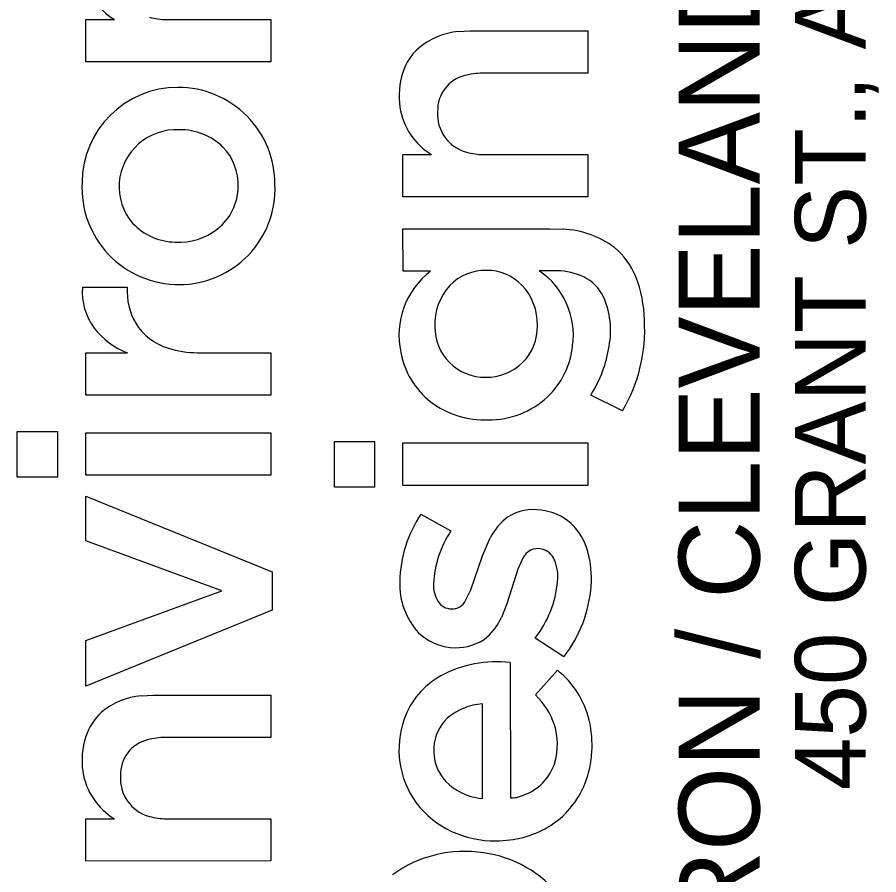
# Model space of a CAD drawing. Extents: x -0.2 to 34, y 0 to 22.
# Drawn here: x 32.377 to 32.984, y 3.278 to 3.882 of the extents above; entities that cross this region are included whole.
import ezdxf

# ---------------------------------------------------------------- set-up
doc = ezdxf.new("R2010")
doc.units = 0
doc.layers.add('RW_X_Esmt_SH', color=7, linetype='Continuous')

msp = doc.modelspace()

# ---------------------------------------------------------------- linework, layer by layer
at = {"layer": 'RW_X_Esmt_SH'}
for p, q in [((32.42542, 3.88066), (32.44552, 3.88071)), ((32.42542, 3.85086), (32.42542, 3.88066)), ((32.48222, 3.88071), (32.55569, 3.88071)), ((32.55569, 3.88071), (32.55571, 3.85096)), ((32.68784, 3.8722), (32.69634, 3.87266)), ((32.69634, 3.87266), (32.77916, 3.87266)), ((32.77916, 3.87266), (32.77917, 3.84287)), ((32.55571, 3.85096), (32.42542, 3.85086)), ((32.77917, 3.84287), (32.70485, 3.8428)), ((32.64888, 3.7855), (32.66897, 3.78555)), ((32.64888, 3.75569), (32.64888, 3.7855)), ((32.70568, 3.78555), (32.77915, 3.78555)), ((32.77915, 3.78555), (32.77917, 3.75579)), ((32.77917, 3.75579), (32.64888, 3.75569)), ((32.6489, 3.70336), (32.64889, 3.73322)), ((32.64889, 3.73322), (32.75236, 3.73322)), ((32.75236, 3.73322), (32.76191, 3.73285)), ((32.66836, 3.70336), (32.6489, 3.70336)), ((32.75763, 3.70356), (32.74487, 3.70361)), ((32.42299, 3.69193), (32.45454, 3.69193)), ((32.42542, 3.64577), (32.45473, 3.64579)), ((32.42542, 3.61593), (32.42542, 3.64577)), ((32.50413, 3.64581), (32.55571, 3.64573)), ((32.55571, 3.64573), (32.55565, 3.61593)), ((32.55565, 3.61593), (32.42542, 3.61593)), ((32.8036, 3.60491), (32.7812, 3.61598)), ((32.37705, 3.55818), (32.37705, 3.59026)), ((32.37705, 3.59026), (32.40543, 3.59026)), ((32.40543, 3.59026), (32.40543, 3.55818)), ((32.42542, 3.55942), (32.42542, 3.58928)), ((32.42542, 3.58928), (32.55571, 3.58928)), ((32.55571, 3.58928), (32.55571, 3.55942)), ((32.60051, 3.55111), (32.60051, 3.58319)), ((32.60051, 3.58319), (32.62889, 3.58319)), ((32.62889, 3.58319), (32.62889, 3.55111)), ((32.64888, 3.55234), (32.64888, 3.5822)), ((32.64888, 3.5822), (32.77917, 3.5822)), ((32.77917, 3.5822), (32.77917, 3.55234)), ((32.40543, 3.55818), (32.37705, 3.55818)), ((32.55571, 3.55942), (32.42542, 3.55942)), ((32.77917, 3.55234), (32.64888, 3.55234)), ((32.62889, 3.55111), (32.60051, 3.55111)), ((32.42542, 3.51327), (32.42542, 3.5446)), ((32.42542, 3.5446), (32.5567, 3.4913)), ((32.66151, 3.53207), (32.68268, 3.52025)), ((32.70483, 3.50258), (32.71036, 3.51526)), ((32.52117, 3.47798), (32.42542, 3.51327)), ((32.69675, 3.47868), (32.70483, 3.50258)), ((32.73342, 3.50101), (32.72985, 3.4933)), ((32.5567, 3.4913), (32.5567, 3.46441)), ((32.72985, 3.4933), (32.72213, 3.46882)), ((32.42542, 3.44294), (32.52117, 3.47798)), ((32.69299, 3.47117), (32.69675, 3.47868)), ((32.72213, 3.46882), (32.71822, 3.45921)), ((32.5567, 3.46441), (32.42542, 3.41086)), ((32.42542, 3.41086), (32.42542, 3.44294)), ((32.76214, 3.43141), (32.74198, 3.44469)), ((32.72453, 3.42747), (32.72463, 3.33195)), ((32.74228, 3.40465), (32.75768, 3.422)), ((32.46439, 3.40397), (32.47289, 3.40443)), ((32.47289, 3.40443), (32.55571, 3.40443)), ((32.55571, 3.40443), (32.55571, 3.37465)), ((32.70489, 3.33182), (32.70489, 3.39834)), ((32.55571, 3.37465), (32.4814, 3.37457)), ((32.70361, 3.33165), (32.70489, 3.33182)), ((32.42542, 3.31728), (32.44552, 3.31733)), ((32.42542, 3.28747), (32.42542, 3.31728)), ((32.48222, 3.31733), (32.55569, 3.31733)), ((32.55569, 3.31733), (32.55571, 3.28756)), ((32.55571, 3.28756), (32.42542, 3.28747))]:
    msp.add_line(p, q, dxfattribs=at)
for points in [[(32.42542, 3.85086), (32.42542, 3.88066), (32.44552, 3.88071)], [(32.48222, 3.88071), (32.55569, 3.88071), (32.55571, 3.85096), (32.42542, 3.85086)], [(32.68784, 3.8722), (32.69634, 3.87266), (32.77916, 3.87266), (32.77917, 3.84287), (32.70485, 3.8428)], [(32.64888, 3.75569), (32.64888, 3.7855), (32.66897, 3.78555)], [(32.70568, 3.78555), (32.77915, 3.78555), (32.77917, 3.75579), (32.64888, 3.75569)], [(32.66836, 3.70336), (32.6489, 3.70336), (32.64889, 3.73322), (32.75236, 3.73322), (32.76191, 3.73285)], [(32.75763, 3.70356), (32.74487, 3.70361)], [(32.42299, 3.69193), (32.45454, 3.69193)], [(32.50413, 3.64581), (32.55571, 3.64573), (32.55565, 3.61593), (32.42542, 3.61593)], [(32.42542, 3.61593), (32.42542, 3.64577), (32.45473, 3.64579)], [(32.8036, 3.60491), (32.7812, 3.61598)], [(32.66151, 3.53207), (32.68268, 3.52025)], [(32.69299, 3.47117), (32.69675, 3.47868), (32.70483, 3.50258), (32.71036, 3.51526)], [(32.73342, 3.50101), (32.72985, 3.4933), (32.72213, 3.46882), (32.71822, 3.45921)], [(32.76214, 3.43141), (32.74198, 3.44469)], [(32.72453, 3.42747), (32.72463, 3.33195)], [(32.74228, 3.40465), (32.75768, 3.422)], [(32.46439, 3.40397), (32.47289, 3.40443), (32.55571, 3.40443), (32.55571, 3.37465), (32.4814, 3.37457)], [(32.70361, 3.33165), (32.70489, 3.33182), (32.70489, 3.39834)], [(32.42542, 3.28747), (32.42542, 3.31728), (32.44552, 3.31733)], [(32.48222, 3.31733), (32.55569, 3.31733), (32.55571, 3.28756), (32.42542, 3.28747)]]:
    msp.add_lwpolyline(points, dxfattribs=at)
for points in [[(32.37705, 3.55818), (32.37705, 3.59026), (32.40543, 3.59026), (32.40543, 3.55818)], [(32.42542, 3.55942), (32.42542, 3.58928), (32.55571, 3.58928), (32.55571, 3.55942)], [(32.60051, 3.55111), (32.60051, 3.58319), (32.62889, 3.58319), (32.62889, 3.55111)], [(32.64888, 3.55234), (32.64888, 3.5822), (32.77917, 3.5822), (32.77917, 3.55234)], [(32.42542, 3.41086), (32.42542, 3.44294), (32.52117, 3.47798), (32.42542, 3.51327), (32.42542, 3.5446), (32.5567, 3.4913), (32.5567, 3.46441)]]:
    msp.add_lwpolyline(points, close=True, dxfattribs=at)
for centre, radius, start, end in [((32.47027, 3.92141), 0.04763, 188.96462, 238.69865), ((32.47027, 3.92141), 0.04763, 188.96462, 238.69865), ((32.48183, 3.92286), 0.04215, 254.08913, 270.52838), ((32.48183, 3.92286), 0.04215, 254.08913, 270.52838), ((32.69216, 3.82251), 0.04988, 94.97056, 130.22484), ((32.69216, 3.82251), 0.04988, 94.97056, 130.22484), ((32.68694, 3.83085), 0.04016, 132.22383, 161.68229), ((32.68694, 3.83085), 0.04016, 132.22383, 161.68229), ((32.70217, 3.82642), 0.05602, 162.27398, 187.79173), ((32.70217, 3.82642), 0.05602, 162.27398, 187.79173), ((32.69828, 3.81689), 0.02498, 103.68683, 182.21395), ((32.69828, 3.81689), 0.02498, 103.68683, 182.21395), ((32.70453, 3.79679), 0.04601, 89.60515, 105.33026), ((32.70453, 3.79679), 0.04601, 89.60515, 105.33026), ((32.49014, 3.76543), 0.0674, 89.84756, 179.64047), ((32.49014, 3.76543), 0.0674, 89.84756, 179.64047), ((32.49057, 3.76474), 0.0681, 359.54009, 90.21138), ((32.49057, 3.76474), 0.0681, 359.54009, 90.21138), ((32.69372, 3.82624), 0.04763, 188.96462, 238.69865), ((32.69372, 3.82624), 0.04763, 188.96462, 238.69865), ((32.7008, 3.81381), 0.02757, 175.58441, 255.13816), ((32.7008, 3.81381), 0.02757, 175.58441, 255.13816), ((32.48923, 3.76263), 0.0404, 87.04809, 175.57259), ((32.48923, 3.76263), 0.0404, 87.04809, 175.57259), ((32.49204, 3.75999), 0.04299, 45.84264, 90.98008), ((32.49204, 3.75999), 0.04299, 45.84264, 90.98008), ((32.49458, 3.76421), 0.03821, 357.88569, 44.15902), ((32.49458, 3.76421), 0.03821, 357.88569, 44.15902), ((32.70529, 3.82769), 0.04215, 254.08913, 270.52838), ((32.70529, 3.82769), 0.04215, 254.08913, 270.52838), ((32.49083, 3.76209), 0.06819, 176.8344, 270.40384), ((32.49083, 3.76209), 0.06819, 176.8344, 270.40384), ((32.48729, 3.7625), 0.03848, 175.15378, 221.14706), ((32.48729, 3.7625), 0.03848, 175.15378, 221.14706), ((32.49123, 3.76139), 0.06749, 270.06243, 2.37759), ((32.49123, 3.76139), 0.06749, 270.06243, 2.37759), ((32.49446, 3.76318), 0.0383, 308.28936, 359.43468), ((32.49446, 3.76318), 0.0383, 308.28936, 359.43468), ((32.48919, 3.76607), 0.04228, 223.09994, 268.80895), ((32.48919, 3.76607), 0.04228, 223.09994, 268.80895), ((32.49096, 3.7679), 0.04418, 266.56515, 308.06078), ((32.49096, 3.7679), 0.04418, 266.56515, 308.06078), ((32.75907, 3.66789), 0.06503, 53.40344, 87.49062), ((32.75907, 3.66789), 0.06503, 53.40344, 87.49062), ((32.76517, 3.68039), 0.05141, 21.60748, 50.5577), ((32.76517, 3.68039), 0.05141, 21.60748, 50.5577), ((32.70292, 3.65813), 0.05692, 127.37482, 192.22468), ((32.70292, 3.65813), 0.05692, 127.37482, 192.22468), ((32.70693, 3.66927), 0.0346, 88.47302, 136.42562), ((32.70693, 3.66927), 0.0346, 88.47302, 136.42562), ((32.70814, 3.66963), 0.03424, 44.27195, 90.47623), ((32.70814, 3.66963), 0.03424, 44.27195, 90.47623), ((32.71421, 3.65829), 0.05472, 352.1125, 55.92295), ((32.71421, 3.65829), 0.05472, 352.1125, 55.92295), ((32.75666, 3.65725), 0.04633, 65.01687, 88.8011), ((32.75666, 3.65725), 0.04633, 65.01687, 88.8011), ((32.7626, 3.67155), 0.03085, 26.26808, 63.80301), ((32.7626, 3.67155), 0.03085, 26.26808, 63.80301), ((32.73069, 3.66714), 0.08835, 1.15143, 21.3627), ((32.73069, 3.66714), 0.08835, 1.15143, 21.3627), ((32.46616, 3.68882), 0.04329, 175.87313, 216.34747), ((32.46616, 3.68882), 0.04329, 175.87313, 216.34747), ((32.50087, 3.68948), 0.04639, 176.9688, 209.60636), ((32.50087, 3.68948), 0.04639, 176.9688, 209.60636), ((32.71141, 3.66602), 0.0401, 137.46739, 182.33237), ((32.71141, 3.66602), 0.0401, 137.46739, 182.33237), ((32.70368, 3.666), 0.03996, 358.57141, 43.53765), ((32.70368, 3.666), 0.03996, 358.57141, 43.53765), ((32.73565, 3.66154), 0.05953, 349.30734, 23.43071), ((32.73565, 3.66154), 0.05953, 349.30734, 23.43071), ((32.70538, 3.66244), 0.11383, 329.6388, 3.25998), ((32.70538, 3.66244), 0.11383, 329.6388, 3.25998), ((32.47466, 3.69716), 0.05511, 218.09809, 248.7907), ((32.47466, 3.69716), 0.05511, 218.09809, 248.7907), ((32.49514, 3.68814), 0.04079, 211.94466, 253.2028), ((32.49514, 3.68814), 0.04079, 211.94466, 253.2028), ((32.70645, 3.6637), 0.03511, 178.88208, 271.08374), ((32.70645, 3.6637), 0.03511, 178.88208, 271.08374), ((32.70818, 3.66404), 0.03546, 268.27882, 1.55016), ((32.70818, 3.66404), 0.03546, 268.27882, 1.55016), ((32.50465, 3.7165), 0.07069, 252.46555, 269.57296), ((32.50465, 3.7165), 0.07069, 252.46555, 269.57296), ((32.70988, 3.65708), 0.05887, 313.74196, 353.8554), ((32.70988, 3.65708), 0.05887, 313.74196, 353.8554), ((32.70738, 3.66334), 0.08771, 327.31495, 351.57478), ((32.70738, 3.66334), 0.08771, 327.31495, 351.57478), ((32.70463, 3.65696), 0.05837, 190.75182, 231.28919), ((32.70463, 3.65696), 0.05837, 190.75182, 231.28919), ((32.70954, 3.65901), 0.06051, 269.6361, 312.70877), ((32.70954, 3.65901), 0.06051, 269.6361, 312.70877), ((32.70632, 3.66112), 0.06269, 232.46061, 272.59022), ((32.70632, 3.66112), 0.06269, 232.46061, 272.59022), ((32.7406, 3.5026), 0.03263, 80.17192, 122.51969), ((32.7406, 3.5026), 0.03263, 80.17192, 122.51969), ((32.74278, 3.49824), 0.03667, 47.79344, 84.68918), ((32.74278, 3.49824), 0.03667, 47.79344, 84.68918), ((32.73636, 3.48258), 0.08973, 146.53104, 178.7571), ((32.73636, 3.48258), 0.08973, 146.53104, 178.7571), ((32.74661, 3.49713), 0.04053, 125.51182, 153.41595), ((32.74661, 3.49713), 0.04053, 125.51182, 153.41595), ((32.73788, 3.4946), 0.04267, 14.9966, 46.20632), ((32.73788, 3.4946), 0.04267, 14.9966, 46.20632), ((32.74519, 3.4789), 0.07495, 146.51121, 176.91007), ((32.74519, 3.4789), 0.07495, 146.51121, 176.91007), ((32.74384, 3.49631), 0.01143, 76.66094, 155.7053), ((32.74384, 3.49631), 0.01143, 76.66094, 155.7053), ((32.74397, 3.49511), 0.01256, 21.5098, 78.52618), ((32.74397, 3.49511), 0.01256, 21.5098, 78.52618), ((32.71044, 3.48674), 0.07121, 355.83062, 15.39138), ((32.71044, 3.48674), 0.07121, 355.83062, 15.39138), ((32.72592, 3.48766), 0.03209, 354.57264, 22.06805), ((32.72592, 3.48766), 0.03209, 354.57264, 22.06805), ((32.69666, 3.48238), 0.05005, 177.53659, 222.79318), ((32.69666, 3.48238), 0.05005, 177.53659, 222.79318), ((32.6931, 3.48233), 0.02276, 178.47474, 211.08679), ((32.6931, 3.48233), 0.02276, 178.47474, 211.08679), ((32.68248, 3.49149), 0.0757, 321.81101, 354.79685), ((32.68248, 3.49149), 0.0757, 321.81101, 354.79685), ((32.68952, 3.4882), 0.09219, 321.9777, 355.87384), ((32.68952, 3.4882), 0.09219, 321.9777, 355.87384), ((32.68331, 3.4767), 0.01148, 212.23676, 268.37769), ((32.68331, 3.4767), 0.01148, 212.23676, 268.37769), ((32.68342, 3.47589), 0.01067, 267.71603, 333.73375), ((32.68342, 3.47589), 0.01067, 267.71603, 333.73375), ((32.68098, 3.4758), 0.04077, 308.08772, 335.98736), ((32.68098, 3.4758), 0.04077, 308.08772, 335.98736), ((32.68599, 3.47535), 0.0375, 225.98539, 302.47965), ((32.68599, 3.47535), 0.0375, 225.98539, 302.47965), ((32.7152, 3.34414), 0.08384, 83.61499, 118.28755), ((32.7152, 3.34414), 0.08384, 83.61499, 118.28755), ((32.71744, 3.37167), 0.06443, 13.53365, 51.36148), ((32.71744, 3.37167), 0.06443, 13.53365, 51.36148), ((32.70239, 3.36906), 0.05583, 118.83082, 160.62438), ((32.70239, 3.36906), 0.05583, 118.83082, 160.62438), ((32.46871, 3.35428), 0.04988, 94.96958, 130.22249), ((32.46871, 3.35428), 0.04988, 94.96958, 130.22249), ((32.70378, 3.36556), 0.05486, 19.03571, 45.44059), ((32.70378, 3.36556), 0.05486, 19.03571, 45.44059), ((32.70785, 3.35609), 0.04235, 94.00805, 130.88169), ((32.70785, 3.35609), 0.04235, 94.00805, 130.88169), ((32.46348, 3.36263), 0.04015, 132.22192, 161.68183), ((32.46348, 3.36263), 0.04015, 132.22192, 161.68183), ((32.70048, 3.36628), 0.02985, 132.98507, 177.179), ((32.70048, 3.36628), 0.02985, 132.98507, 177.179), ((32.71041, 3.36612), 0.06437, 160.52012, 215.78311), ((32.71041, 3.36612), 0.06437, 160.52012, 215.78311), ((32.71069, 3.3697), 0.047, 344.60586, 17.007), ((32.71069, 3.3697), 0.047, 344.60586, 17.007), ((32.70635, 3.36921), 0.07579, 339.3542, 13.37853), ((32.70635, 3.36921), 0.07579, 339.3542, 13.37853), ((32.47872, 3.35819), 0.05601, 162.27355, 187.79185), ((32.47872, 3.35819), 0.05601, 162.27355, 187.79185), ((32.47482, 3.34867), 0.02498, 103.68646, 182.21874), ((32.47482, 3.34867), 0.02498, 103.68646, 182.21874), ((32.48108, 3.32856), 0.04601, 89.60494, 105.3284), ((32.48108, 3.32856), 0.04601, 89.60494, 105.3284), ((32.7017, 3.36503), 0.03115, 175.00126, 223.28301), ((32.7017, 3.36503), 0.03115, 175.00126, 223.28301), ((32.7224, 3.36715), 0.03504, 288.00773, 343.55078), ((32.7224, 3.36715), 0.03504, 288.00773, 343.55078), ((32.47026, 3.35802), 0.04762, 188.96199, 238.70369), ((32.47026, 3.35802), 0.04762, 188.96199, 238.70369), ((32.47735, 3.34558), 0.02756, 175.58538, 255.14386), ((32.47735, 3.34558), 0.02756, 175.58538, 255.14386), ((32.70891, 3.37363), 0.04231, 225.06188, 262.79738), ((32.70891, 3.37363), 0.04231, 225.06188, 262.79738), ((32.71894, 3.3652), 0.0626, 300.94269, 338.73225), ((32.71894, 3.3652), 0.0626, 300.94269, 338.73225), ((32.72474, 3.35216), 0.02021, 269.7003, 294.8711), ((32.72474, 3.35216), 0.02021, 269.7003, 294.8711), ((32.71253, 3.37054), 0.06872, 217.74516, 271.65431), ((32.71253, 3.37054), 0.06872, 217.74516, 271.65431), ((32.48183, 3.35948), 0.04215, 254.09162, 270.52835), ((32.48183, 3.35948), 0.04215, 254.09162, 270.52835), ((32.71549, 3.37241), 0.07056, 269.20477, 300.33412), ((32.71549, 3.37241), 0.07056, 269.20477, 300.33412), ((32.69229, 3.20792), 0.08641, 81.19402, 125.99844), ((32.69229, 3.20792), 0.08641, 81.19402, 125.99844), ((32.69458, 3.21132), 0.08272, 37.85208, 82.40204), ((32.69458, 3.21132), 0.08272, 37.85208, 82.40204)]:
    msp.add_arc(centre, radius, start, end, dxfattribs=at)

# ---------------------------------------------------------------- texts
for s, height, p in [('450 GRANT ST., AKRON, OH  44311', 0.0498462, (32.97489, 3.33738)), ('AKRON / CLEVELAND / COLUMBUS', 0.056969, (32.90012, 3.138))]:
    msp.add_text(s, height=height, rotation=90, dxfattribs=at).set_placement(p)

doc.saveas('drawing.dxf')
